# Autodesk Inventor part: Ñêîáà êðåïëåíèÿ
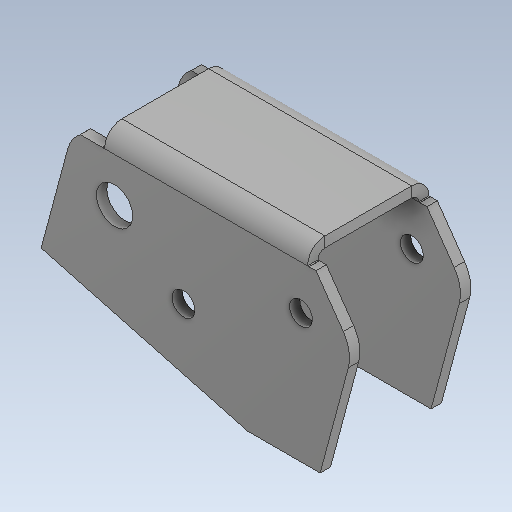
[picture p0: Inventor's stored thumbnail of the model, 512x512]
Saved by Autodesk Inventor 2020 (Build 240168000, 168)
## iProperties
Created: 1900-01
Part Number: Ñêîáà êðåïëåíèÿ
Material: Générique
Document SubType Name: Modeling
Designer: bruno
Density: 1 g/cm^3
Appearance: Par défaut
Author: bruno
Revision Number: ANYUNSPECIFIED
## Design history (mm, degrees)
feature "Base1"
node "Solide1"
